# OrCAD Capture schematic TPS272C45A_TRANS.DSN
size E; title: TPS272C45A: 45-mOhm, Dual-Channel Smart High-Side Switch; rev: 1.0; note: Datasheet: SLVSF24     EVM: SLVUBV4; note: with Diagnostics
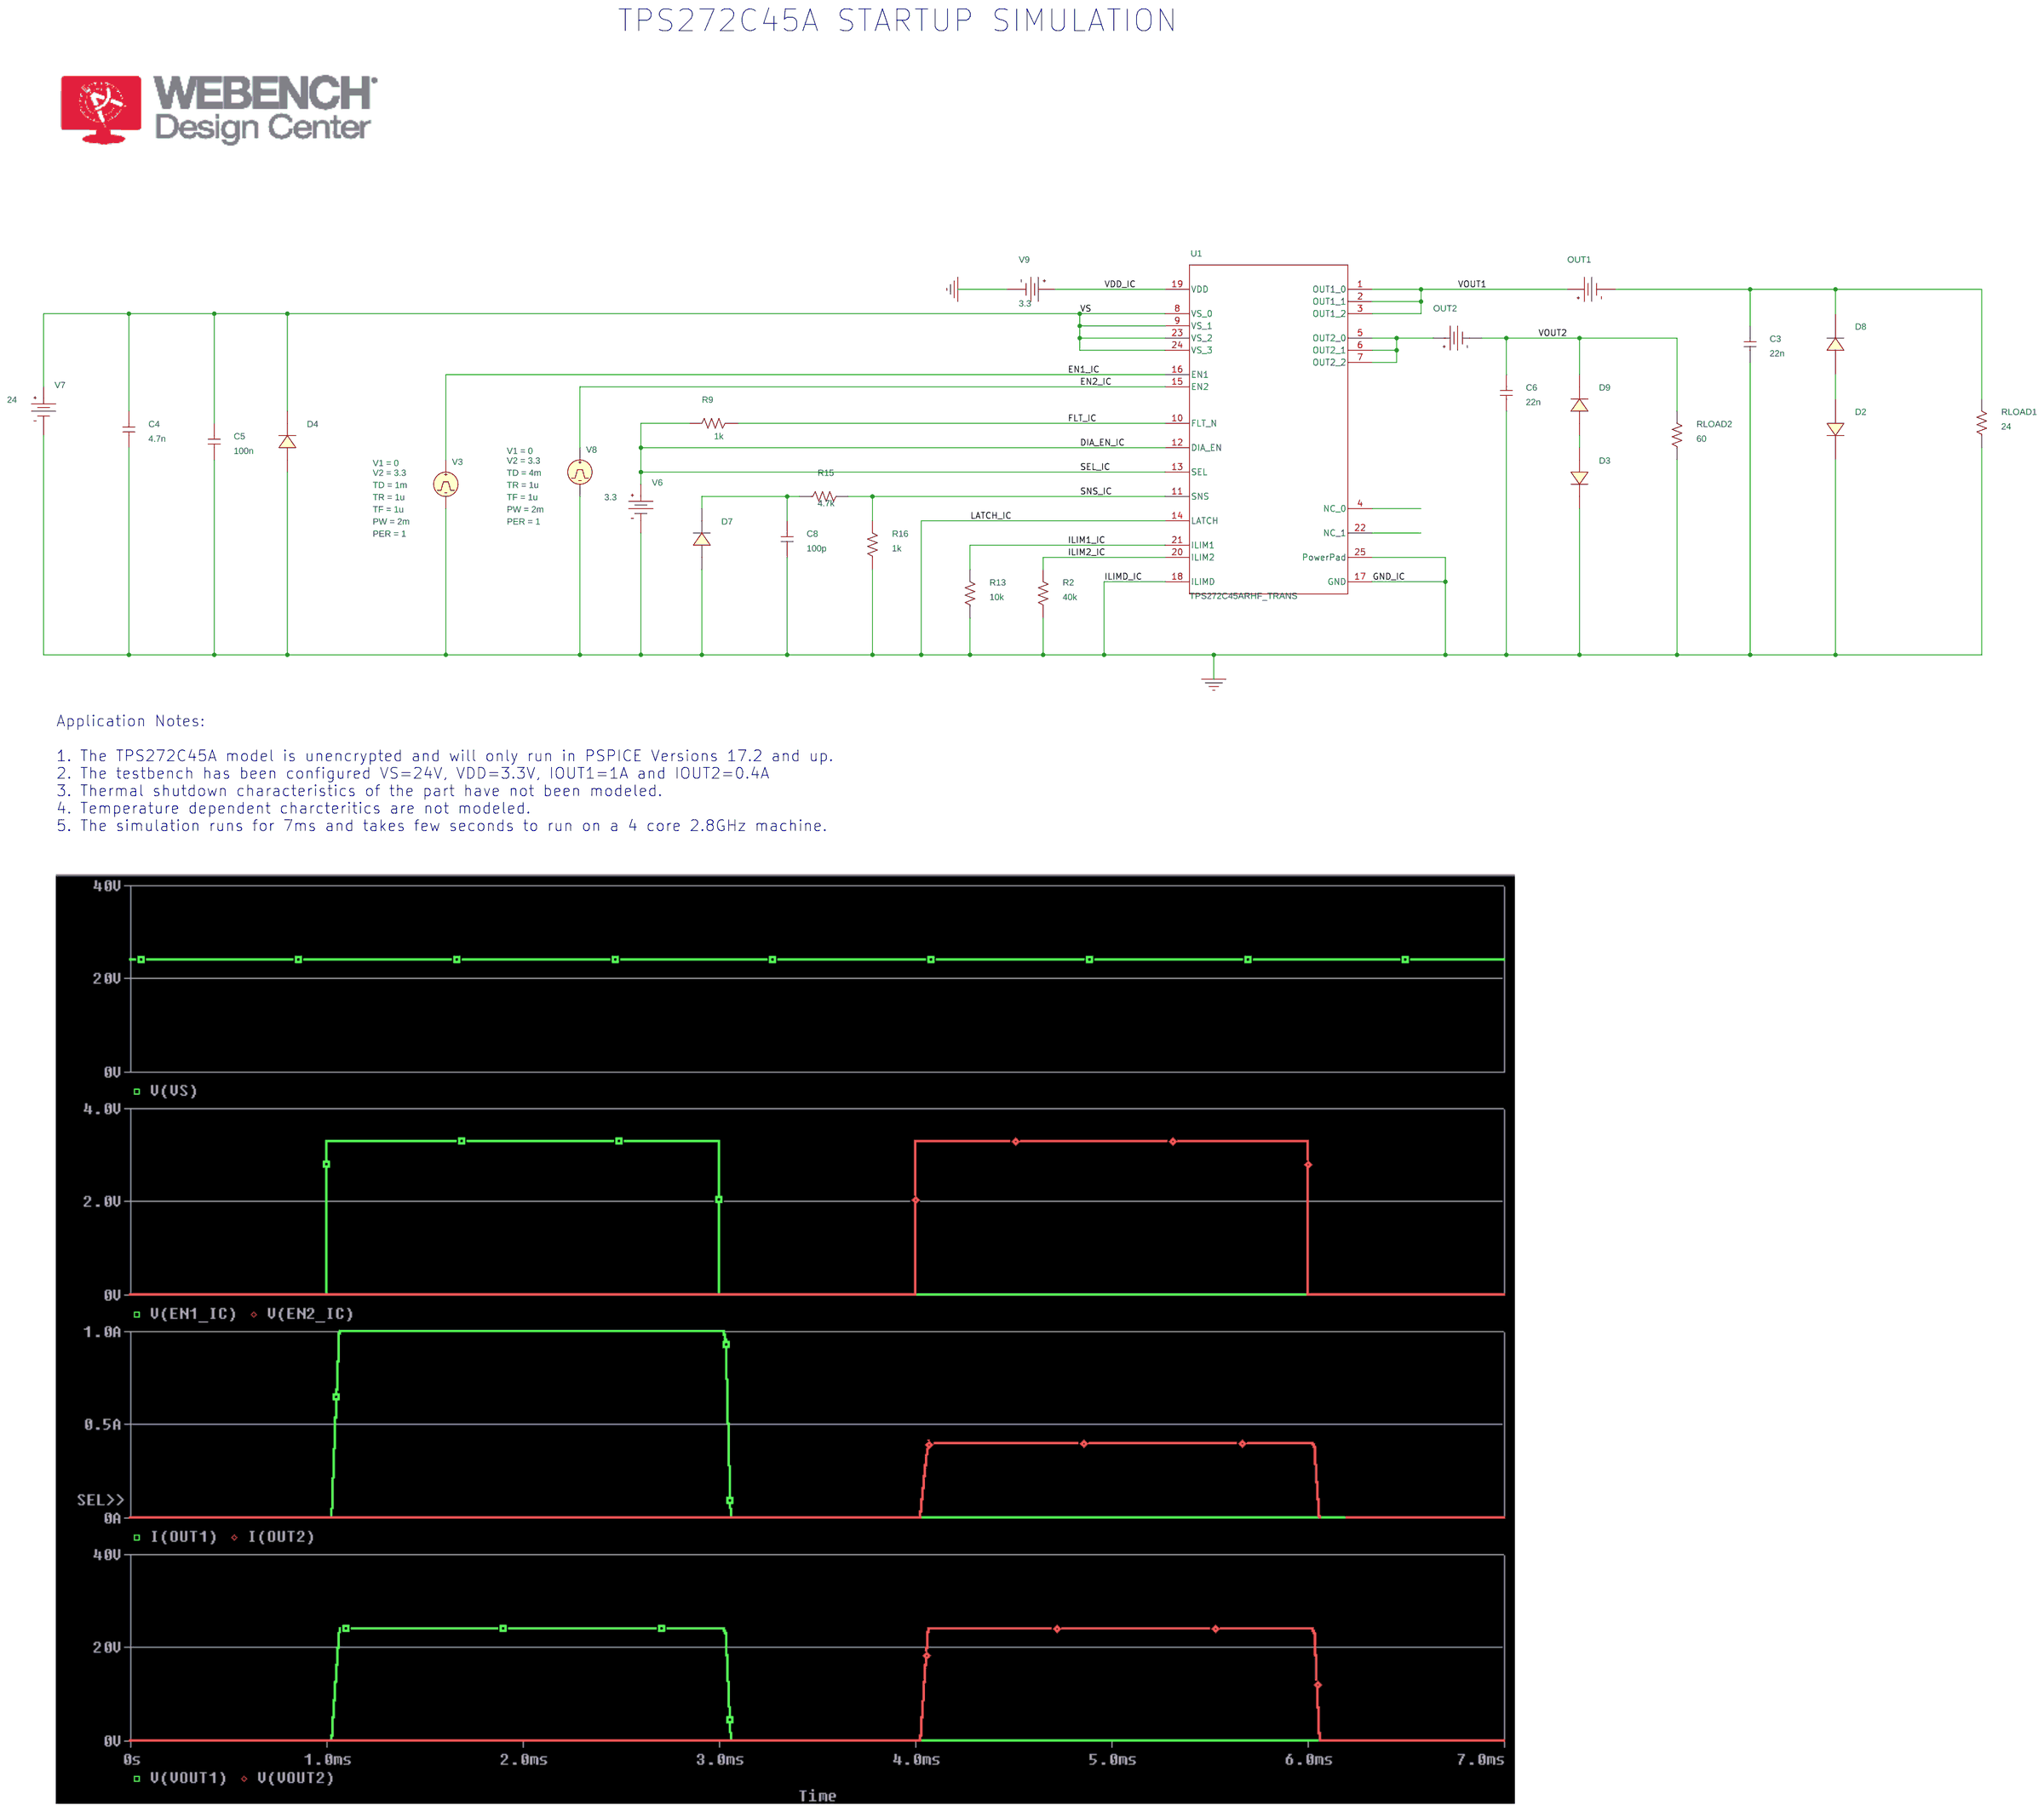
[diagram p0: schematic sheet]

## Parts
C3  22n  [RAD/CK05]
C4  4.7n  [RAD/CK05]
C5  100n  [RAD/CK05]
C6  22n  [RAD/CK05]
C8  100p  [RAD/CK05]
D2  SMAJ48A
D3  SMAJ48A
D4  SMBJ33A
D7  MMSZ5226B
D8  STPS1150A  [SMA]
D9  STPS1150A  [SMA]
OUT1  VDC
OUT2  VDC
R2  40k  [AX/RC05]
R9  1k  [AX/RC05]
R13  10k  [AX/RC05]
R15  4.7k  [AX/RC05]
R16  1k  [AX/RC05]
RLOAD1  24  [AX/RC05]
RLOAD2  60  [AX/RC05]
U1  TPS272C45ARHF_TRANS  [RHF0024A-IPC_A]
V3  VPULSE
V6  VDC
V7  VDC
V8  VPULSE
V9  VDC

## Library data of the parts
C3-C6 C8 = C
D2-D4 = DD
D7 = DD: PSpiceTemplate: X^@REFDES  %A %C @MODEL
D8 D9 = STPS1150A
OUT1 OUT2 = VDC
R2 R9 R13 R15 R16 RLOAD1 RLOAD2 = R
U1 = TPS272C45ARHF_TRANS
V3 = VPULSE: PER: 1; PW: 2m; TD: 1m; TF: 1u; TR: 1u; V1: 0; V2: 3.3
V6 V9 = VDC: DC: 3.3
V7 = VDC: DC: 24
V8 = VPULSE: PER: 1; PW: 2m; TD: 4m; TF: 1u; TR: 1u; V1: 0; V2: 3.3

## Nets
VDD_IC: U1.19(VDD) V9.0(+)
0: C3.1 C4.1 C5.1 C6.1 C8.1 D2.1(C) D3.1(C) D4.2(A) D7.2(A) R2.1 R13.1 R16.1 RLOAD1.1 RLOAD2.1 U1.14(LATCH) U1.17(GND) U1.18(ILIMD) U1.25(PowerPad) V3.2(-) V6.1(-) V7.1(-) V8.2(-) V9.1(-)
DIA_EN_IC: R9.2 U1.12(DIA_EN) U1.13(SEL) V6.0(+)
EN1_IC: U1.16(EN1) V3.1(+)
EN2_IC: U1.15(EN2) V8.1(+)
FLT_IC: R9.1 U1.10(FLT_N)
ILIM1_IC: R13.2 U1.21(ILIM1)
ILIM2_IC: R2.2 U1.20(ILIM2)
SNS_IC: R15.2 R16.2 U1.11(SNS)
VOUT1: OUT1.0(+) U1.1(OUT1_0) U1.2(OUT1_1) U1.3(OUT1_2)
VOUT2: C6.2 D9.1(C) OUT2.1(-) RLOAD2.2
VS: C4.2 C5.2 D4.1(C) U1.8(VS_0) U1.9(VS_1) U1.23(VS_2) U1.24(VS_3) V7.0(+)
N01721: C8.2 D7.1(C) R15.1
N03147: C3.2 D8.1(C) OUT1.1(-) RLOAD1.2
N03499: D2.2(A) D8.2(A)
N03590: OUT2.0(+) U1.5(OUT2_0) U1.6(OUT2_1) U1.7(OUT2_2)
N03893: D3.2(A) D9.2(A)

Not connected (* = marked no-connect by the designer): U1 4(NC_0) 22(NC_1)

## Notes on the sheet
- TPS272C45A STARTUP SIMULATION
- Application Notes:
  1. The TPS272C45A model is unencrypted and will only run in PSPICE Versions 17.2 and up.
  2. The testbench has been configured VS=24V, VDD=3.3V, IOUT1=1A and IOUT2=0.4A
  3. Thermal shutdown characteristics of the part have not been modeled.
  4. Temperature dependent charcteritics are not modeled.
  5. The simulation runs for 7ms and takes few seconds to run on a 4 core 2.8GHz machine.
